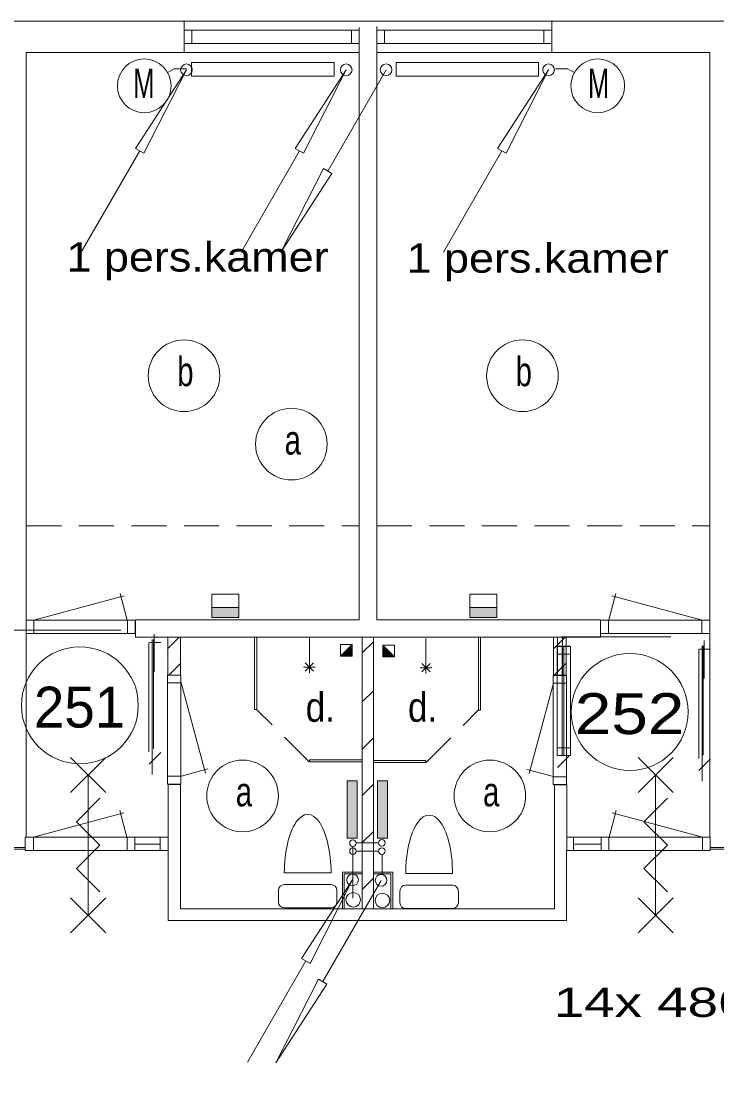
# Model space of a CAD drawing. Extents: x 295824 to 414724, y 24924 to 109024.
# Drawn here: x 308047 to 314001, y 95404 to 104418 of the extents above; entities that cross this region are included whole.
import ezdxf
from ezdxf.enums import TextEntityAlignment as Align

# ---------------------------------------------------------------- set-up
doc = ezdxf.new("R2010")
doc.units = 0
doc.header["$LTSCALE"] = 100
doc.linetypes.add('LONG_DASHED', pattern=[7.5, 6, -1.5])
doc.linetypes.add('MEDIUM_DASHED', pattern=[4.5, 3, -1.5])
doc.layers.add('16', color=7, linetype='Continuous', lineweight=13)
doc.layers.add('61', color=7, linetype='Continuous', lineweight=13)

msp = doc.modelspace()

# ---------------------------------------------------------------- hatches: boundary and pattern name
at = {"layer": '16'}
for points in [[(309911.3, 99315.2), (309679.8, 99315.2), (309679.8, 99401.7), (309911.3, 99401.7)], [(312117.3, 99315.2), (311885.8, 99315.2), (311885.8, 99401.7), (312117.3, 99401.7)], [(310838.6, 97919.8), (310924, 97919.8), (310924, 97427.7), (310838.6, 97427.7)], [(311097.8, 97919.8), (311183.2, 97919.8), (311183.2, 97427.7), (311097.8, 97427.7)]]:
    msp.add_hatch(color=256, dxfattribs=at).paths.add_polyline_path(points)
at = {"layer": '61'}
for points in [[(310781.4, 98986.3), (310881.4, 99086.3), (310881.4, 98986.3)], [(311243.8, 98980.9), (311143.8, 99080.9), (311143.8, 98980.9)]]:
    msp.add_hatch(color=256, dxfattribs=at).paths.add_polyline_path(points)

# ---------------------------------------------------------------- linework, layer by layer
at = {"layer": '16'}
for p, q in [((311170.8, 104000.9), (310670.8, 103134.9)), ((308562.5, 102441.9), (309062.5, 103307.9)), ((309929.1, 102441.9), (310429.1, 103307.9)), ((311661, 102441.9), (312161, 103307.9)), ((309679.8, 99401.7), (309679.8, 99515.6)), ((311885.8, 99401.7), (311885.8, 99515.6)), ((310885.9, 96917), (310885.9, 97353.4)), ((311106.2, 97388.8), (310914.5, 97388.8)), ((311127.8, 97067.7), (310627.8, 96201.7)), ((309983.9, 95512.9), (310483.9, 96378.9))]:
    msp.add_line(p, q, dxfattribs=at)
at = {"layer": '16', "linetype": 'LONG_DASHED'}
for p, q in [((310914.6, 97318.1), (311106.1, 97318.1)), ((311137.1, 97128.8), (311137.1, 97292.3))]:
    msp.add_line(p, q, dxfattribs=at)
at = {"layer": '16'}
for points in [[(309506.4, 103945.4), (310725.8, 103945.4), (310725.8, 104063.3), (309506.4, 104063.3)], [(311255.3, 103945.4), (312474.7, 103945.4), (312474.7, 104063.3), (311255.3, 104063.3)], [(309462.5, 104000.9), (309098.5, 103286.9), (309026.5, 103328.9)], [(310829.1, 104000.9), (310465.1, 103286.9), (310393.1, 103328.9)], [(312561, 104000.9), (312197, 103286.9), (312125, 103328.9)], [(310270.8, 102441.9), (310634.8, 103155.9), (310706.8, 103113.9)], [(309911.3, 99315.2), (309679.8, 99315.2), (309679.8, 99401.7), (309911.3, 99401.7)], [(312117.3, 99315.2), (311885.8, 99315.2), (311885.8, 99401.7), (312117.3, 99401.7)], [(310838.6, 97919.8), (310924, 97919.8), (310924, 97427.7), (310838.6, 97427.7)], [(311097.8, 97919.8), (311183.2, 97919.8), (311183.2, 97427.7), (311097.8, 97427.7)], [(310883.9, 97071.9), (310519.9, 96357.9), (310447.9, 96399.9)], [(310227.8, 95508.7), (310591.8, 96222.7), (310663.8, 96180.7)]]:
    msp.add_lwpolyline(points, close=True, dxfattribs=at)
for points in [[(309462.5, 104008.7), (309356.5, 104008.7), (309297, 103974.4)], [(312619.9, 104008.7), (312725.9, 104008.7), (312785.4, 103974.4)], [(309911.3, 99401.7), (309911.3, 99515.6), (309679.8, 99515.6)], [(312117.3, 99401.7), (312117.3, 99515.6), (311885.8, 99515.6)]]:
    msp.add_lwpolyline(points, dxfattribs=at)
for centre, radius in [((309101.4, 103863.4), 229.9), ((309462.5, 104000.6), 50), ((310829.1, 104000.6), 50), ((311170.8, 104001.3), 50), ((312561, 104000.6), 50), ((312981, 103863.4), 229.9), ((310886.7, 97385.9), 27.9), ((311134.1, 97388.8), 27.9), ((310886.7, 97318.1), 27.9), ((311134.1, 97318.1), 27.9), ((310883.9, 97071.6), 50), ((311127.8, 97068), 50)]:
    msp.add_circle(centre, radius, dxfattribs=at)
at = {"layer": '61'}
for p, q in [((309441.5, 104147.6), (309441.5, 104417.6)), ((312589.8, 104147.6), (312589.8, 104416.9)), ((309508.3, 104225.9), (309508.3, 104339.8)), ((310873.3, 104225.3), (310873.3, 104339.3)), ((311156.8, 104226.2), (311156.8, 104340.2)), ((312521.1, 104225.9), (312521.1, 104339.6)), ((308090.1, 104147.6), (310940.1, 104147.6)), ((308090.1, 97436.7), (308090.1, 104147.6)), ((313940.1, 104147.6), (311090.1, 104147.6)), ((313940.1, 97436.7), (313940.1, 104147.6)), ((308955, 99294.3), (308894.2, 99521.1)), ((313075.3, 99295.4), (313136.1, 99522.2)), ((308156.5, 99293.7), (308929.3, 99500.7)), ((313873.7, 99294.8), (313101, 99501.8)), ((308157.3, 99179), (308157.3, 99293)), ((308957.3, 99179), (308957.3, 99293)), ((309024.3, 99179), (309024.3, 99293)), ((313005.2, 99297.6), (313005.2, 99147.6)), ((313006, 99180.1), (313006, 99294.1)), ((313073, 99180.1), (313073, 99294.1)), ((313873, 99180.1), (313873, 99294.1)), ((308900.2, 99206.9), (307966.2, 99206.9)), ((309186.9, 98850.8), (309186.9, 99174.9)), ((313605.4, 99151.2), (312671.4, 99151.2)), ((309139.9, 98166.6), (309139.9, 99100.6)), ((309242.1, 99101.4), (309147.4, 99101.4)), ((309168.7, 98194.5), (309168.7, 99128.5)), ((309179.7, 98194.5), (309179.7, 99128.5)), ((309301.2, 99048), (309400.9, 99147.7)), ((309302.7, 98824.2), (309302.7, 99148.3)), ((309302.7, 99148.3), (309412.6, 99148.3)), ((309412.6, 98824.2), (309412.6, 99148.3)), ((310063.9, 99148.6), (310063.9, 98528.1)), ((310513.8, 98942.1), (310513.8, 99142.1)), ((310965.8, 99148.9), (310965.8, 96823.9)), ((310966.3, 99012.7), (311062.1, 99108.5)), ((311062.1, 99148.9), (311062.1, 96823.9)), ((311511.5, 98936.8), (311511.5, 99136.8)), ((311961.3, 99143.2), (311961.3, 98522.8)), ((312601.6, 98824.2), (312601.6, 99148.3)), ((312601.6, 99148.3), (312711.6, 99148.3)), ((312603.3, 99048), (312703, 99147.7)), ((312636.6, 98823), (312636.6, 99147)), ((312743.2, 99072.1), (312638, 99072.1)), ((312676.7, 98136.1), (312676.7, 99068.5)), ((312679.3, 98823), (312679.3, 99147)), ((312692.5, 98136.1), (312692.5, 99068.5)), ((312711.6, 98824.2), (312711.6, 99148.3)), ((312749.2, 98136.1), (312749.2, 99068.5)), ((313873.8, 98138.8), (313873.8, 99072.8)), ((313884.9, 98138.8), (313884.9, 99072.8)), ((313892, 98795.1), (313892, 99119.2)), ((312749.2, 99001.5), (312635.2, 99001.5)), ((313845, 98110.9), (313845, 99044.9)), ((313947.3, 99045.7), (313852.5, 99045.7)), ((309170.2, 98905.7), (309170.2, 97973.3)), ((309313.5, 98825.4), (309413.2, 98925.1)), ((310563.8, 98892.1), (310463.8, 98892.1)), ((310549.1, 98927.4), (310478.4, 98856.7)), ((310549.1, 98856.7), (310478.4, 98927.4)), ((310513.8, 98942.1), (310513.8, 98842.1)), ((311461.5, 98886.8), (311561.5, 98886.8)), ((311476.1, 98922.1), (311546.8, 98851.4)), ((311476.1, 98851.4), (311546.8, 98922.1)), ((311511.5, 98936.8), (311511.5, 98836.8)), ((312611.9, 98825.4), (312711.6, 98925.1)), ((309300.9, 98823.3), (309300.9, 97890.9)), ((309302.7, 98824.2), (309412.6, 98824.2)), ((312600.9, 98820.7), (312714.9, 98820.7)), ((312601.6, 98824.2), (312711.6, 98824.2)), ((312714.3, 98820.7), (312714.3, 97886.7)), ((313875.3, 98850), (313875.3, 97917.6)), ((309300.9, 98757.9), (309414.9, 98757.9)), ((309418, 98758.7), (309625.1, 97985.9)), ((312602.3, 98754.4), (312395.2, 97981.7)), ((312714.3, 98753.7), (312600.3, 98753.7)), ((310966.3, 98594.6), (311062.1, 98690.4)), ((310966.3, 98190), (311062.1, 98285.8)), ((309242.3, 98161.9), (309142.6, 98062.2)), ((312749.2, 98201.5), (312635.2, 98201.5)), ((308771.2, 98119.9), (308471.2, 97819.9)), ((308471.2, 98119.9), (308771.2, 97819.9)), ((310963.9, 98098.6), (310514.8, 98098.6)), ((310514.8, 98080.6), (310514.8, 98098.6)), ((310964.3, 98080.6), (310514.8, 98080.6)), ((311061, 98075.2), (311510.4, 98075.2)), ((311061.3, 98093.2), (311510.4, 98093.2)), ((311510.4, 98075.2), (311510.4, 98093.2)), ((312736.6, 98134), (312636.9, 98034.3)), ((312747.4, 98135.2), (312637.4, 98135.2)), ((313627, 98119.9), (313327, 97819.9)), ((313327, 98119.9), (313627, 97819.9)), ((313947.4, 98106.1), (313847.7, 98006.4)), ((309418.7, 97960.3), (309645.5, 98021)), ((312601.6, 97956), (312374.8, 98016.8)), ((308621.2, 96769.9), (308621.2, 97969.9)), ((309300.9, 97957.9), (309414.9, 97957.9)), ((310966.3, 97794), (311062.1, 97889.8)), ((312714.3, 97953.7), (312600.3, 97953.7)), ((313477, 96769.9), (313477, 97969.9)), ((309306.8, 97887.3), (309306.8, 97321.5)), ((309306.8, 97887.3), (309412.1, 97887.3)), ((312612.1, 97885.9), (312612.1, 96823.9)), ((312612.1, 97885.9), (312706.8, 97885.9)), ((312716.7, 97885.9), (312716.7, 97423.9)), ((308153.2, 97437.3), (308925.9, 97644.4)), ((308951.6, 97437.9), (308890.8, 97664.8)), ((313078.9, 97437.9), (313139.7, 97664.8)), ((313877.3, 97437.3), (313104.6, 97644.4)), ((310966.3, 97390.7), (311062.1, 97486.4)), ((307944.7, 97348.9), (308085.9, 97348.9)), ((308153.9, 97322.7), (308153.9, 97436.7)), ((308953.9, 97322.7), (308953.9, 97436.7)), ((309020.9, 97322.7), (309020.9, 97436.7)), ((309238.6, 97376.8), (309020.9, 97376.8)), ((309238.6, 97323.9), (309238.6, 97437.9)), ((312775.3, 97323.9), (312775.3, 97437.9)), ((312783.6, 97376.8), (313009.6, 97376.8)), ((313009.6, 97322.7), (313009.6, 97436.7)), ((313076.6, 97322.7), (313076.6, 97436.7)), ((313876.6, 97322.7), (313876.6, 97436.7)), ((313944.8, 97348.9), (314086, 97348.9)), ((307944.7, 97333.9), (308085.9, 97333.9)), ((312715.1, 96722.6), (312715.1, 97322.6)), ((313944.8, 97333.9), (314086, 97333.9)), ((310699.5, 97131.8), (310299.5, 97131.8)), ((310812, 97124.3), (310962, 97124.3)), ((310812, 96824.3), (310812, 97124.3)), ((310966.3, 96989.8), (311062.1, 97085.5)), ((311062.1, 97123.9), (311212.1, 97123.9)), ((311212.1, 97123.9), (311212.1, 96823.9)), ((311738.9, 97126.8), (311338.9, 97126.8)), ((310299.5, 97031.8), (310699.5, 97031.8)), ((311338.9, 97026.8), (311738.9, 97026.8)), ((308771.2, 96919.9), (308471.2, 96619.9)), ((308471.2, 96919.9), (308771.2, 96619.9)), ((310249.5, 96881.8), (310249.5, 96981.8)), ((310749.5, 96981.8), (310749.5, 96881.8)), ((311288.9, 96876.8), (311288.9, 96976.8)), ((311788.9, 96976.8), (311788.9, 96876.8)), ((313627, 96919.9), (313327, 96619.9)), ((313327, 96919.9), (313627, 96619.9)), ((310699.5, 96831.8), (310299.5, 96831.8)), ((311738.9, 96826.8), (311338.9, 96826.8))]:
    msp.add_line(p, q, dxfattribs=at)
at = {"layer": '61', "linetype": 'MEDIUM_DASHED'}
for p, q in [((308091.8, 100101), (310940.1, 100101)), ((311090.6, 100101), (313940.8, 100101)), ((310512.7, 98081), (310065.8, 98527.9)), ((311512.5, 98075.7), (311959.4, 98522.6))]:
    msp.add_line(p, q, dxfattribs=at)
at = {"layer": '61'}
for points in [[(301796.6, 92184.5), (301820.1, 104417.6), (332210.1, 104417.6)], [(310940.1, 104361.7), (310940.1, 99297.6), (309025.1, 99297.6), (309025.1, 99147.6), (313005.2, 99147.6)], [(311090.1, 104370.5), (311090.1, 99297.6), (313005.2, 99297.6)], [(308090.3, 99179), (308090.3, 99293), (309024.3, 99293)], [(309024.3, 99179), (308090.3, 99179), (308090.3, 99293)], [(313940, 99180.1), (313940, 99294.1), (313006, 99294.1)], [(313006, 99180.1), (313940, 99180.1), (313940, 99294.1)], [(310045.9, 99148.6), (310045.9, 98528.1), (310063.9, 98528.1)], [(310881.4, 99086.3), (310881.4, 98986.3), (310781.4, 98986.3)], [(311143.8, 99080.9), (311143.8, 98980.9), (311243.8, 98980.9)], [(311979.3, 99143.2), (311979.3, 98522.8), (311961.3, 98522.8)], [(309412.1, 97887.3), (309412.1, 96823.9), (312612.1, 96823.9)], [(308721.2, 96969.9), (308521.2, 97169.9), (308721.2, 97369.9), (308521.2, 97569.9), (308721.2, 97769.9)], [(313577, 96969.9), (313377, 97169.9), (313577, 97369.9), (313377, 97569.9), (313577, 97769.9)], [(309306.8, 97323.9), (309306.8, 96723.9), (312706.8, 96723.9)], [(310797, 96824.3), (310797, 97139.3), (310962, 97139.3)], [(311062.1, 97138.9), (311227.1, 97138.9), (311227.1, 96823.9)]]:
    msp.add_lwpolyline(points, dxfattribs=at)
for points in [[(309441.5, 104225.8), (309441.5, 104339.8), (310940.1, 104339.8), (310940.1, 104225.8)], [(311090.5, 104225.9), (311090.5, 104339.9), (312589.8, 104339.9), (312589.8, 104225.9)], [(310881.4, 99086.3), (310781.4, 99086.3), (310781.4, 98986.3)], [(310781.4, 98986.3), (310881.4, 99086.3), (310881.4, 98986.3)], [(311143.8, 99080.9), (311243.8, 99080.9), (311243.8, 98980.9)], [(311243.8, 98980.9), (311143.8, 99080.9), (311143.8, 98980.9)], [(312749.2, 99069.4), (312635.2, 99069.4), (312635.2, 98135.4), (312749.2, 98135.4)], [(309300.9, 97890), (309414.9, 97890), (309414.9, 98824), (309300.9, 98824)], [(312714.3, 98820.7), (312714.3, 97886.7), (312600.3, 97886.7), (312600.3, 98820.7)], [(308080.8, 97322.7), (308080.8, 97436.7), (309307.2, 97436.7), (309307.2, 97322.7)], [(312716.6, 97322.7), (312716.6, 97436.7), (313943.6, 97436.7), (313943.6, 97322.7)]]:
    msp.add_lwpolyline(points, close=True, dxfattribs=at)
for centre, radius in [((309441.3, 101384.2), 306.3), ((312336.8, 101384.2), 306.3), ((310360.1, 100799.1), 306.3), ((308550.2, 98564.7), 500), ((313255.3, 98509), 500), ((309942.5, 97790.1), 306.3), ((312058.4, 97790.1), 306.3), ((310889.6, 96901.8), 62.5), ((311139.6, 96896.3), 62.5)]:
    msp.add_circle(centre, radius, dxfattribs=at)
for centre, start, end in [((310299.5, 96981.8), 90, 180), ((310699.5, 96981.8), 0, 90), ((311338.9, 96976.8), 90, 180), ((311738.9, 96976.8), 0, 90), ((310299.5, 96881.8), 180, 270), ((310699.5, 96881.8), 270, 0), ((311338.9, 96876.8), 180, 270), ((311738.9, 96876.8), 270, 0)]:
    msp.add_arc(centre, 50, start, end, dxfattribs=at)
for centre in [(310499.5, 97131.8), (311538.9, 97126.8)]:
    msp.add_ellipse(centre, major_axis=(0, 500), ratio=0.4, start_param=4.712389, end_param=7.853982, dxfattribs=at)

# ---------------------------------------------------------------- texts
at = {"layer": '16'}
for s, width, p in [('M', 0.65, (309007.3, 103760.3)), ('M', 0.65, (312897.9, 103760.3)), ('14x 486-900-10', 1.4, (312605.1, 95900.2))]:
    msp.add_text(s, height=250, dxfattribs=dict(at, width=width)).set_placement(p)
at = {"layer": '61'}
for s, width, p in [('1 pers.kamer', 1.15, (308435.4, 102275.4)), ('1 pers.kamer', 1.15, (311345.3, 102265.6)), ('b', 0.75, (309383.3, 101295)), ('b', 0.75, (312278.8, 101295)), ('a', 0.75, (310302.1, 100709.9)), ('d.', 0.9, (310482.7, 98424.3)), ('d.', 0.9, (311357.6, 98424.3)), ('a', 0.75, (309884.5, 97700.9)), ('a', 0.75, (312000.4, 97700.9))]:
    msp.add_text(s, height=250, dxfattribs=dict(at, width=width)).set_placement(p)
msp.add_text('251', height=350, dxfattribs=at).set_placement((308547.3, 98374.8), align=Align.CENTER)
at = {"layer": '61', "width": 1.2}
msp.add_text('252', height=350, dxfattribs=at).set_placement((313253.8, 98319.1), align=Align.CENTER)

doc.saveas('drawing.dxf')
